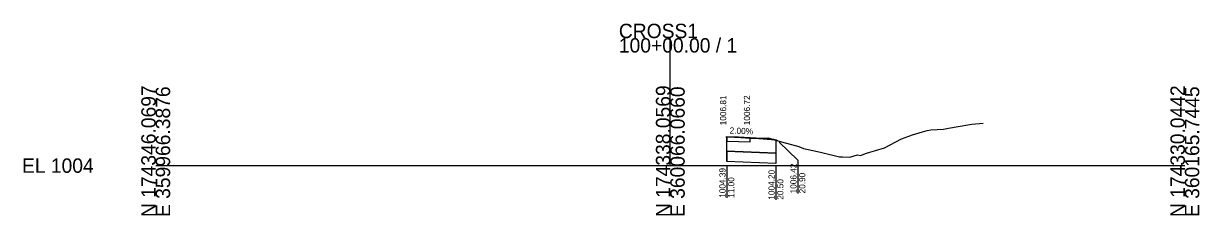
# Model space of a CAD drawing. Extents: x -26 to 1403, y -10 to 11027.
# Drawn here: x 1174.3 to 1402.8, y 3490.3 to 3527.6 of the extents above; entities that cross this region are included whole.
import ezdxf

# ---------------------------------------------------------------- set-up
doc = ezdxf.new("R2010")
doc.units = 0
for name, color, linetype in [('Default', 7, 'Continuous'), ('GSBWFILL', 7, 'Continuous'), ('GSCOLORFILL', 7, 'Continuous'), ('P_XS_EAR_CommonGrnd', 7, 'Continuous'), ('P_XS_Rock', 7, 'Continuous'), ('P_XS_Subgrade', 7, 'Continuous')]:
    doc.layers.add(name, color=color, linetype=linetype)

msp = doc.modelspace()

# ---------------------------------------------------------------- linework, layer by layer
at = {"layer": 'Default'}
for p, q in [((1300, 3500), (1300, 3524.78)), ((1200, 3500), (1300, 3500)), ((1300, 3500), (1400, 3500))]:
    msp.add_line(p, q, dxfattribs=at)
at = {"layer": 'GSBWFILL'}
for p, q in [((1311, 3505.61), (1315.5, 3505.43)), ((1315.5, 3505.43), (1320.5, 3505.03)), ((1320.5, 3505.03), (1320.9, 3504.83))]:
    msp.add_line(p, q, dxfattribs=at)
at = {"layer": 'GSCOLORFILL'}
for p, q in [((1311, 3504.78), (1311, 3505.61)), ((1311, 3504.78), (1315.5, 3504.6)), ((1311, 3502.78), (1311, 3504.78)), ((1315.5, 3504.6), (1315.5, 3505.43)), ((1320.5, 3505.03), (1320.5, 3502.4)), ((1311, 3502.78), (1320.5, 3502.4)), ((1311, 3502.78), (1311, 3500.78)), ((1320.5, 3502.4), (1320.5, 3500.4)), ((1320.5, 3500.4), (1311, 3500.78))]:
    msp.add_line(p, q, dxfattribs=at)
at = {"layer": 'P_XS_EAR_CommonGrnd'}
for points in [[(1311, 3504.78), (1315.5, 3504.6), (1315.5, 3505.37), (1313.73, 3505.45), (1313.26, 3505.52), (1311, 3505.61)], [(1312.77, 3505.6), (1313.26, 3505.52), (1311, 3505.61)], [(1315.5, 3505.37), (1315.97, 3505.35), (1316.69, 3505.34), (1320.13, 3505.06), (1320.5, 3504.95), (1320.5, 3502.4), (1311, 3502.78), (1311, 3504.78), (1315.5, 3504.6)], [(1315.5, 3505.37), (1315.5, 3505.43), (1313.26, 3505.52), (1313.73, 3505.45)], [(1315.5, 3505.37), (1315.97, 3505.35), (1316.69, 3505.34), (1315.5, 3505.43)], [(1317.4, 3505.36), (1318.95, 3505.41), (1320.13, 3505.06), (1316.69, 3505.34), (1316.85, 3505.34)], [(1320.5, 3505.03), (1320.5, 3504.95), (1320.13, 3505.06)], [(1320.5, 3504.95), (1320.9, 3504.83), (1320.5, 3505.03)], [(1311, 3502.78), (1320.5, 3502.4), (1320.5, 3500.4), (1311, 3500.78)]]:
    msp.add_lwpolyline(points, close=True, dxfattribs=at)
at = {"layer": 'P_XS_Rock'}
for p, q in [((1324.78, 3501.06), (1321.15, 3504.59)), ((1310.99, 3500.09), (1310.99, 3493.74)), ((1320.53, 3499.82), (1320.53, 3493.37)), ((1324.78, 3501.06), (1324.78, 3494.6))]:
    msp.add_line(p, q, dxfattribs=at)
at = {"layer": 'P_XS_Subgrade'}
for p, q in [((1357.84, 3507.92), (1358.6, 3508.06)), ((1358.6, 3508.06), (1360.78, 3508.26)), ((1344.96, 3505.21), (1347.1, 3506.01)), ((1347.1, 3506.01), (1349.01, 3506.58)), ((1349.01, 3506.58), (1349.91, 3506.86)), ((1349.91, 3506.86), (1350.65, 3506.95)), ((1350.65, 3506.95), (1353.11, 3507.11)), ((1353.11, 3507.11), (1354.09, 3507.26)), ((1354.09, 3507.26), (1357.84, 3507.92)), ((1310.82, 3505.62), (1312.77, 3505.6)), ((1312.77, 3505.6), (1313.73, 3505.45)), ((1313.73, 3505.45), (1315.97, 3505.35)), ((1315.97, 3505.35), (1316.85, 3505.34)), ((1316.85, 3505.34), (1317.4, 3505.36)), ((1317.4, 3505.36), (1318.95, 3505.41)), ((1318.95, 3505.41), (1321.35, 3504.7)), ((1321.35, 3504.7), (1322.57, 3504.37)), ((1322.57, 3504.37), (1324.98, 3503.75)), ((1324.98, 3503.75), (1325.89, 3503.36)), ((1338.11, 3502.42), (1341.63, 3503.49)), ((1341.63, 3503.49), (1343.84, 3504.64)), ((1343.84, 3504.64), (1344.96, 3505.21)), ((1325.89, 3503.36), (1328.63, 3502.72)), ((1328.63, 3502.72), (1329.46, 3502.57)), ((1329.46, 3502.57), (1332.85, 3501.74)), ((1332.85, 3501.74), (1333.46, 3501.68)), ((1333.46, 3501.68), (1334.87, 3501.63)), ((1334.87, 3501.63), (1336.4, 3502.07)), ((1336.4, 3502.07), (1336.98, 3501.99)), ((1336.98, 3501.99), (1338.11, 3502.42))]:
    msp.add_line(p, q, dxfattribs=at)

# ---------------------------------------------------------------- texts
at = {"layer": 'Default'}
for s, p in [('CROSS1', (1290, 3524.78)), ('100+00.00 / 1', (1290, 3521.98)), ('EL 1004', (1174, 3498.6))]:
    msp.add_text(s, height=2.8, dxfattribs=at).set_placement(p)
for s, p in [('N 174346.0697', (1200, 3490)), ('E 359966.3876', (1202.8, 3490)), ('N 174338.0569', (1300, 3490)), ('E 360066.0660', (1302.8, 3490)), ('N 174330.0442', (1400, 3490)), ('E 360165.7445', (1402.8, 3490))]:
    msp.add_text(s, height=2.8, rotation=90, dxfattribs=at).set_placement(p)
at = {"layer": 'P_XS_Rock'}
for s, rotation, p in [('1006.81', 90, (1310.86, 3507.84)), ('1006.72', 90, (1315.5, 3507.85)), ('2.00%', 357.7094, (1311.51, 3506.24)), ('1004.39', 90, (1310.74, 3493.74)), ('1004.20', 90, (1320.28, 3493.37)), ('1006.42', 90, (1324.53, 3494.6)), ('11.00', 90, (1312.44, 3493.74)), ('20.50', 90, (1321.98, 3493.37)), ('20.90', 90, (1326.23, 3494.6))]:
    msp.add_text(s, height=1.2, rotation=rotation, dxfattribs=at).set_placement(p)

doc.saveas('drawing.dxf')
